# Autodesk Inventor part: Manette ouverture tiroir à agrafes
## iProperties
Author: Flavien MARTY
Shininess: 20.0
PropertySet Name: _Private Model Information
Created: 2001-10
Part Number: Manette ouverture tiroir à agrafes
Material: Par défaut
Document SubType Name: Modélisation
Designer: Flavien MARTY
Control State: 0
Master: False
Checked Out: False
PropertySet Name: Design Tracking Control
Density: 0.0
Volumn: 0.0
Area: 0.0
PropertySet Name: Model Information
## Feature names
1. Base1
